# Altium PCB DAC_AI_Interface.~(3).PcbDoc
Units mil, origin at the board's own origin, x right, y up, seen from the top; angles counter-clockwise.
Board outline 2600 x 10000 mil, 4 copper layers (Top Layer, InternalPlane1, InternalPlane2, Bottom Layer); 6 components, 34 nets, 192 pads, 15 vias.
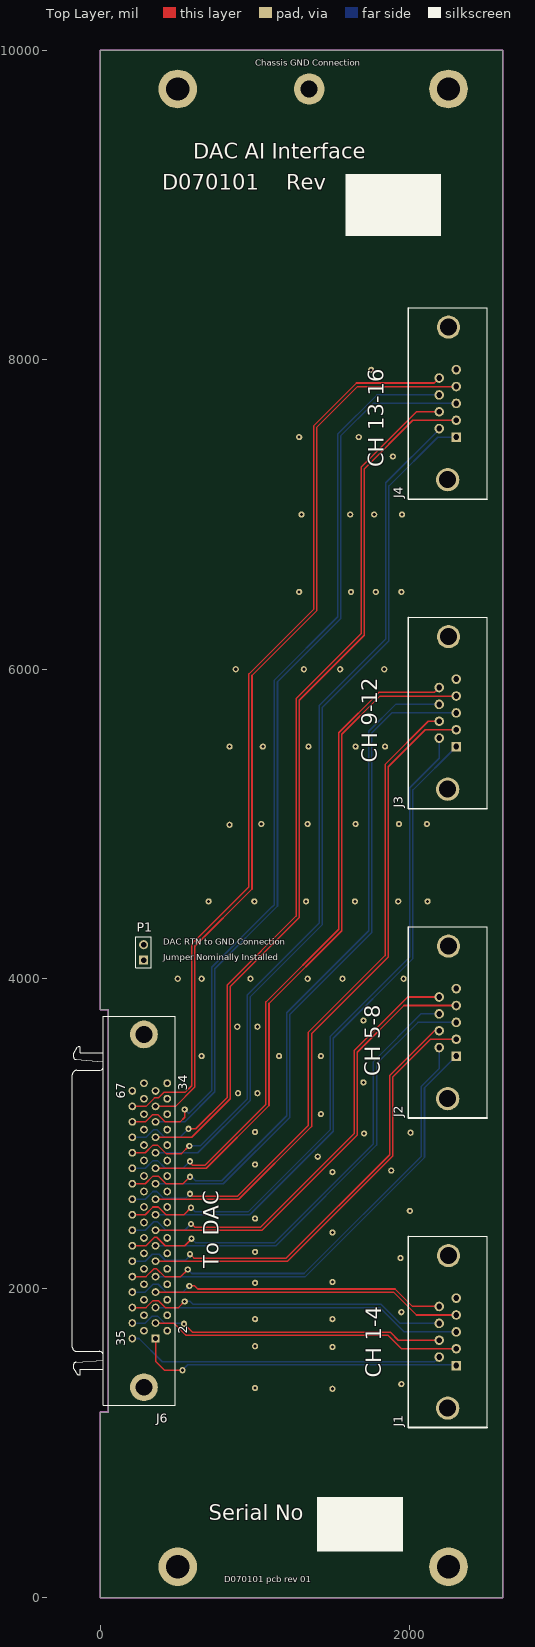
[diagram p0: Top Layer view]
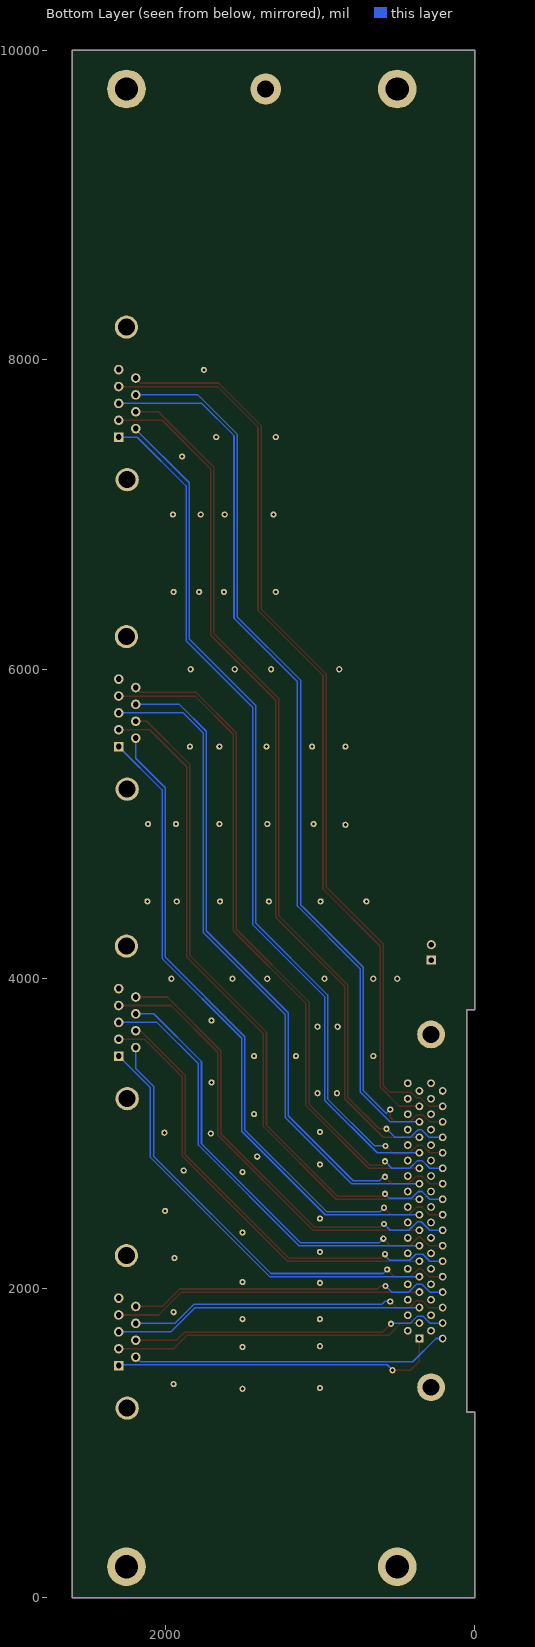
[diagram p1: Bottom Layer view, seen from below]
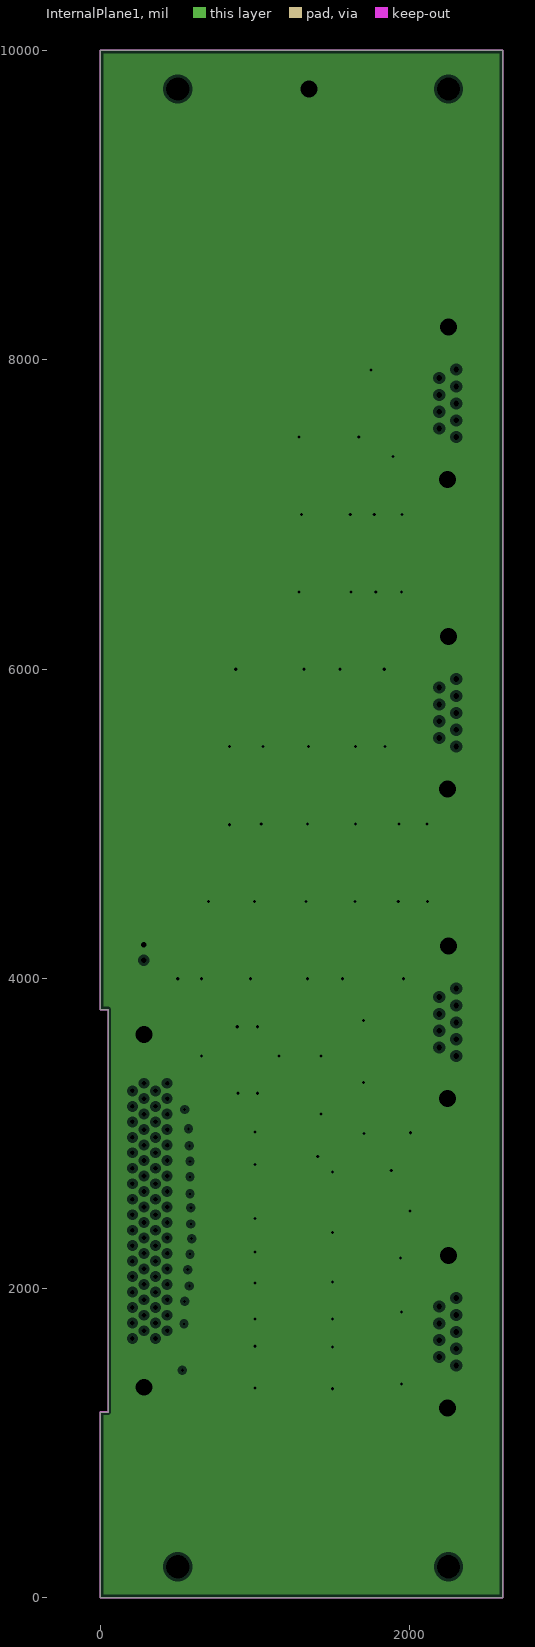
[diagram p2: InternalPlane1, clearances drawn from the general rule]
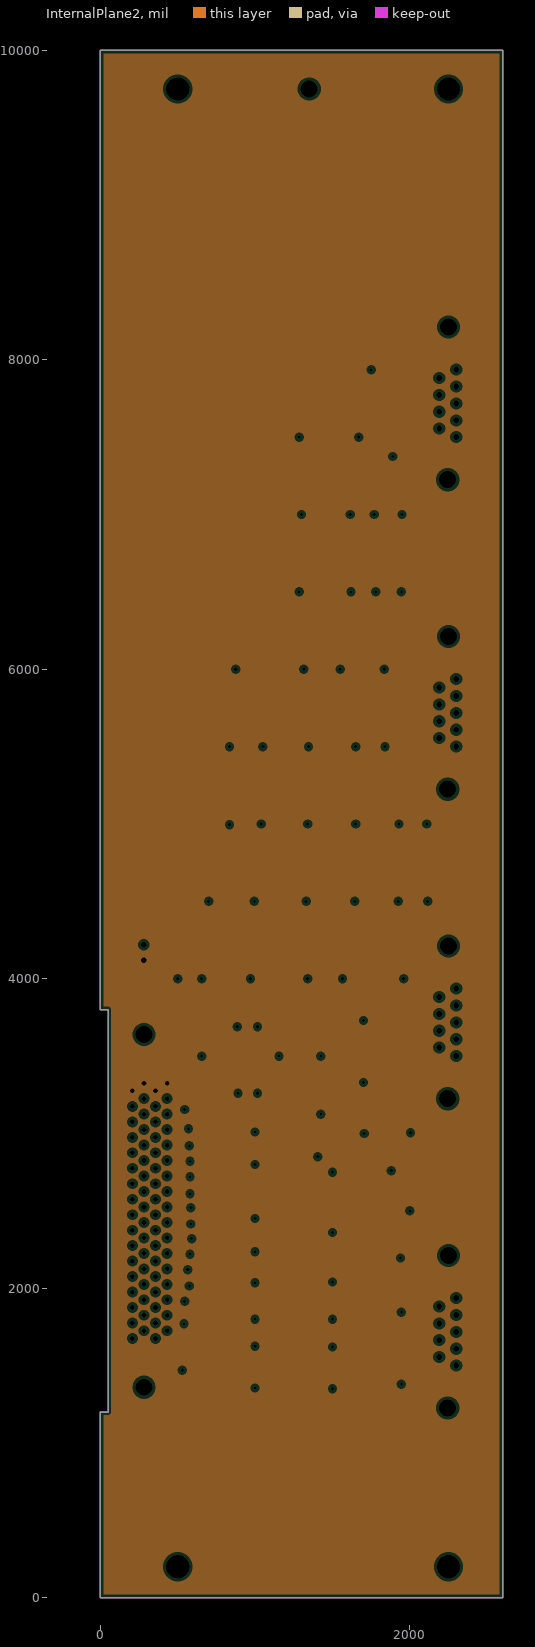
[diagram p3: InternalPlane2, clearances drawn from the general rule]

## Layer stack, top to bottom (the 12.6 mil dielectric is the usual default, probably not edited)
Top Solder: solder mask 0.4, Solder Resist, Dk 3.5
Top Layer: signal copper 1.4
Dielectric1: core 12.6, FR-4, Dk 4.8
InternalPlane1: plane copper 1.4
Dielectric2: prepreg 12.6, FR-4, Dk 4.8
InternalPlane2: plane copper 1.4
Dielectric3: core 12.6, FR-4, Dk 4.8
Bottom Layer: signal copper 1.4
Bottom Solder: solder mask 0.4, Solder Resist, Dk 3.5

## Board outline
0,0 0,1200 50,1200 50,3800 0,3800 0,10000 2600,10000 2600,0

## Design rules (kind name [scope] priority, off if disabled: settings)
Clearance [All] p1: gap=10 ignorepadtopadclearanceinfootprint=FALSE except(0: Arc-Hole Track-Hole SMDPad-Hole THPad-Hole Via-Hole Fill-Hole Poly-Hole Region-Hole Text-Hole)
FabricationTestPointUsage TestPointUsage [All] p1: valid=0 allowmultiple=FALSE
FabricationTestpoint Testpoint [All] p1: side=3 testpointundercomponent=TRUE minsize=40 maxsize=100 preferedsize=60 minholesize=0 maxholesize=40 preferedholesize=32 testpointgrid=1 allowsidetop=TRUE allowsidebottom=TRUE usegrid=TRUE gridtolerance=0.01
HoleSize [All] p1: absolutevalues=TRUE maxlimit=200 minlimit=1 maxpercent=80.000 minpercent=20.000
PlaneClearance [All] p1: clearance=20
PlaneConnect [All] p1: planeconnectstyle=Relief reliefexpansion=20 reliefentries=4 reliefconductorwidth=10 reliefairgap=10
PolygonConnect [All] p1: connectstyle=Relief reliefconductorwidth=10 reliefentries=4 polygonreliefangle="90 Angle" airgapwidth=10
RoutingVias [All] p1: holewidth=20 width=40 viastyle="Through Hole" minholewidth=20 minwidth=40 maxholewidth=28 maxwidth=50
SolderMaskExpansion [All] p1: expansion=4
Width [All] p1: maxlimit=100 minlimit=10 preferedwidth=10
25 further rules are at their usual default settings.

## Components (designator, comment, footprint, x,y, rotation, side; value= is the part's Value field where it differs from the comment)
J1 "5747089-2" DB9/F 2300,1500 r90 top
J2 "5747089-2" DB9/F 2300,3500 r90 top
J3 "5747089-2" DB9/F 2300,5500 r90 top
J4 "5747089-2" DB9/F 2300,7500 r90 top
J6 "787082-7" 787082-7 20,2500 r90 top
P1 "Header 2" HDR1X2 280,4120 r90 top

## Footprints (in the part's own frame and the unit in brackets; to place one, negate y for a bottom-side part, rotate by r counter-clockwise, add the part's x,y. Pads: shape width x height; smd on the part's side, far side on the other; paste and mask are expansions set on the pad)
787082-7 [mm] "Connector; D Subminiature 050 Series; 68 Position; Right Angle"
  rect 1.27x1.27 hole 0.762: 1(-20.955,-8.555)
  round 1.27 hole 0.762: 2(-19.685,-10.46) 3(-18.415,-8.555) 4(-17.145,-10.46) 5(-15.875,-8.555) 6(-14.605,-10.46) 7(-13.335,-8.555) 8(-12.065,-10.46) 9(-10.795,-8.555) 10(-9.525,-10.46) 11(-8.255,-8.555) 12(-6.985,-10.46) 13(-5.715,-8.555) 14(-4.445,-10.46) 15(-3.175,-8.555) 16(-1.905,-10.46) 17(-0.635,-8.555) 18(0.635,-10.46) 19(1.905,-8.555) 20(3.175,-10.46) 21(4.445,-8.555) 22(5.715,-10.46) 23(6.985,-8.555) 24(8.255,-10.46) 25(9.525,-8.555) 26(10.795,-10.46) 27(12.065,-8.555) 28(13.335,-10.46) 29(14.605,-8.555) 30(15.875,-10.46) 31(17.145,-8.555) 32(18.415,-10.46) 33(19.685,-8.555) 34(20.955,-10.46) 35(-20.955,-4.745) 36(-19.685,-6.65) 37(-18.415,-4.745) 38(-17.145,-6.65) 39(-15.875,-4.745) 40(-14.605,-6.65) 41(-13.335,-4.745) 42(-12.065,-6.65) 43(-10.795,-4.745) 44(-9.525,-6.65) 45(-8.255,-4.745) 46(-6.985,-6.65) 47(-5.715,-4.745) 48(-4.445,-6.65) 49(-3.175,-4.745) 50(-1.905,-6.65) 51(-0.635,-4.745) 52(0.635,-6.65) 53(1.905,-4.745) 54(3.175,-6.65) 55(4.445,-4.745) 56(5.715,-6.65) 57(6.985,-4.745) 58(8.255,-6.65) 59(9.525,-4.745) 60(10.795,-6.65) 61(12.065,-4.745) 62(13.335,-6.65) 63(14.605,-4.745) 64(15.875,-6.65) 65(17.145,-4.745) 66(18.415,-6.65) 67(19.685,-4.745) 68(20.955,-6.65)
  round 4.55 hole 2.77: 69(-28.955,-6.65) 70(28.955,-6.65)
  silkscreen extent -31.95,-11.76 31.95,5.11
DB9/F [mil]
  rect 62x62 hole 38: 1(0,0)
  round 62 hole 38: 2(109,0) 3(218,0) 4(327,0) 5(436,0) 6(55,110) 7(164,110) 8(273,110) 9(382,110)
  round 150 hole 110: ""(-275,55) ""(711,50)
  silkscreen extent -400,-200 836,310
HDR1X2 [mm] "Connector; Header; 2 Position"
  rect 1.5x1.5 hole 0.9: 1(0,0)
  round 1.5 hole 0.9: 2(2.54,0)
  silkscreen extent -1.27,-1.27 3.81,1.27

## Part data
J6: "Receptacle Assembly, Shielded, Right Angle, AMPLIMITE"
P1: "Header, 2-Pin"

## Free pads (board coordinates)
  round 200 hole 110: 0(1350,9750)
  round 250 hole 150: 0(2250,200) 1(2250,9750) 2(500,9750) 3(500,200)
  round 40 hole 20: 5(1000,1355) 6(1500,1350) 7(1500,1620) 8(1500,1800) 9(1000,1800) 10(1000,2035) 11(1500,2040) 12(1500,2360) 13(1000,2235) 14(1000,2450) 15(1500,2750) 16(1880,2760) 17(2005,3005) 18(1705,3000) 19(1000,2800) 20(1000,3010) 21(1015,3260) 22(1015,3690) 23(885,3690) 24(890,3260) 25(655,3500) 26(655,4000) 27(970,4000) 28(1340,4000) 29(1565,4000) 30(1960,4000) 31(1700,3330) 32(1405,2850) 33(1425,3125) 34(1425,3500) 35(1700,3730) 36(1155,3500) 37(995,4500) 38(1330,4500) 39(1645,4500) 40(1925,4500) 41(1930,5000) 42(1650,5000) 43(1340,5000) 44(1040,5000) 45(835,4995) 46(700,4500) 47(500,4000) 48(835,5500) 49(1050,5500) 50(1345,5500) 51(1650,5500) 52(1840,5500) 53(1835,6000) 54(1550,6000) 55(1315,6000) 56(875,6000) 57(1620,6500) 58(1780,6500) 59(1945,6500) 60(1285,6500) 61(1300,7000) 62(1615,7000) 63(1770,7000) 64(1950,7000) 65(1890,7375) 66(1670,7500) 67(1285,7500) 68(1750,7935) 69(2115,4500) 70(2110,5000) 71(2000,2500) 72(1945,1845) 73(1945,1380) 74(1940,2195) 75(1000,1625)

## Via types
v1: diameter 40, hole 20, Top Layer to Bottom Layer, 15 vias

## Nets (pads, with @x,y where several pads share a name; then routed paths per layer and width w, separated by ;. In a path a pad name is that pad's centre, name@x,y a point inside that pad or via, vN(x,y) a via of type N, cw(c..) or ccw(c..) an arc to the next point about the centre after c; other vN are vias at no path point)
GND: J1. J2. J3. J4. J6.69 J6.70 P1.2 pad.0@1350,9750 pad.5 pad.6 pad.7 pad.8 pad.9 pad.10 pad.11 pad.12 pad.13 pad.14 pad.15 pad.16 pad.17 pad.18 pad.19 pad.20 pad.21 pad.22 pad.23 pad.24 pad.25 pad.26 pad.27 pad.28 pad.29 pad.30 pad.31 pad.32 pad.33 pad.34 pad.35 pad.36 pad.37 pad.38 pad.39 pad.40 pad.41 pad.42 pad.43 pad.44 pad.45 pad.46 pad.47 pad.48 pad.49 pad.50 pad.51 pad.52 pad.53 pad.54 pad.55 pad.56 pad.57 pad.58 pad.59 pad.60 pad.61 pad.62 pad.63 pad.64 pad.65 pad.66 pad.67 pad.68 pad.69 pad.70 pad.71 pad.72 pad.73 pad.74 pad.75
INPUTN1: J1.6 J6.35 | length 2082.7
  Top Layer w10: J1.6@2165,1555 J1.6
  Bottom Layer w10: J6.35 250,1675 400,1525 2160,1525 J1.6
INPUTN2: J1.7 J6.37 | length 2066.4
  Top Layer w10: v1(540,1770) 595,1715 1875,1715 1926,1664 J1.7
  Bottom Layer w10: J6.37 290,1775 335,1820 370,1820 415,1775 535,1775 v1(540,1770)
INPUTN3: J1.8 J6.39 | length 2095.9
  Top Layer w10: J6.39 295,1875 340,1920 375,1920 420,1875 505,1875 v1(545,1915)
  Bottom Layer w10: v1(545,1915) 580,1915 600,1895 1815,1895 1937,1773 J1.8
INPUTN4: J1.9 J6.41 | length 2096.3
  Top Layer w10: v1(575,2015) 610,2015 630,1995 1905,1995 2018,1882 J1.9
  Bottom Layer w10: J6.41 290,1975 340,2025 375,2025 425,1975 535,1975 v1(575,2015)
INPUTN5: J2.6 J6.43 | length 3002
  Top Layer w10: J6.43 295,2075 345,2125 365,2125 415,2075 520,2075 v1(565,2120)
  Bottom Layer w10: v1(565,2120) 590,2095 1316.72,2095 2075,2853.28 2075,3305 2190,3420 J2.6
INPUTN6: J2.7 J6.45 | length 2959.4
  Top Layer w10: v1(580,2220) 605,2195 1201.72,2195 1870,2863.28 1870,3375 2159,3664 J2.7
  Bottom Layer w10: J6.45 290,2175 335,2220 380,2220 420,2180 550,2180 580,2210 v1(580,2220)
INPUTN7: J2.8 J6.47 | length 2981.4
  Top Layer w10: J6.47 295,2275 350,2330 365,2330 420,2275 545,2275 v1(590,2320)
  Bottom Layer w10: v1(590,2320) 615,2295 1126.72,2295 1765,2933.28 1765,3465 2073,3773 J2.8
INPUTN8: J2.9 J6.49 | length 2983.9
  Top Layer w10: v1(585,2415) 590,2415 610,2395 1036.72,2395 1640,2998.28 1640,3535 1987,3882 J2.9
  Bottom Layer w10: J6.49 290,2375 345,2430 370,2430 425,2375 545,2375 v1(585,2415)
INPUTN9: J3.6 J6.51 | length 4391.2
  Top Layer w10: J6.51 290,2475 340,2525 375,2525 425,2475 540,2475 v1(585,2520)
  Bottom Layer w10: v1(585,2520) 610,2495 956.72,2495 1485,3023.28 1485,3625 2000,4140 2000,5235 2190,5425 J3.6
INPUTN10: J3.7 J6.53 | length 4388.3
  Top Layer w10: v1(580,2610) 595,2595 886.72,2595 1345,3053.28 1345,3655 1840,4150 1840,5385 2119,5664 J3.7
  Bottom Layer w10: J6.53 290,2575 340,2625 365,2625 410,2580 550,2580 v1(580,2610)
INPUTN11: J3.8 J6.55 | length 4473.8
  Top Layer w10: J6.55 290,2675 340,2725 375,2725 425,2675 535,2675 v1(580,2720)
  Bottom Layer w10: v1(580,2720) 590,2720 615,2695 785,2695 1205,3115 1205,3780 1735,4310 1735,5600 1908,5773 J3.8
INPUTN12: J3.9 J6.57 | length 4469.7
  Top Layer w10: v1(580,2820) 580,2810 595,2795 676.72,2795 1070,3188.28 1070,3850 1540,4320 1540,5590 1800,5850 2158,5850 J3.9
  Bottom Layer w10: J6.57 290,2775 340,2825 370,2825 420,2775 535,2775 v1(580,2820)
INPUTN13: J4.6 J6.59 | length 5778.4
  Top Layer w10: J6.59 290,2875 340,2925 370,2925 425,2870 525,2870 v1(575,2920)
  Bottom Layer w10: v1(575,2920) 646.72,2920 950,3223.28 950,3895 1415,4360 1415,5765 1845,6195 1845,7205 2190,7550 J4.6
INPUTN14: J4.7 J6.61 | length 5845.3
  Top Layer w10: v1(570,3030) 616.72,3030 820,3233.28 820,3960 1265,4405 1265,5810 1685,6230 1685,7305 2044,7664 J4.7
  Bottom Layer w10: J6.61 295,2975 345,3025 365,3025 415,2975 515,2975 v1(570,3030)
INPUTN15: J4.8 J6.63 | length 6025.5
  Top Layer w10: J6.63 290,3075 335,3120 375,3120 420,3075 515,3075 545,3105 v1(545,3155)
  Bottom Layer w10: v1(545,3155) 570.86,3129.14 720,3278.28 720,4075 1110,4465 1111.72,4465 1125,4478.28 1125,5930 1535,6340 1535,7520 1788,7773 J4.8
INPUTN16: J4.9 J6.65 | length 5969.5
  Top Layer w10: J6.65 295,3175 350,3230 375,3230 410,3265 546.72,3265 590,3308.28 590,4225 960,4595 960,5970 1380,6390 1380,7575 1655,7850 2158,7850 J4.9
INPUTP1: J1.1 J6.1 | length 2130.7
  Top Layer w10: J6.1 356.81,1528.19 415,1470 v1(530,1470)
  Bottom Layer w10: v1(530,1470) 565,1505 2295,1505 J1.1
INPUTP2: J1.2 J6.3 | length 2011.9
  Top Layer w10: J6.3 475,1775 555,1695 1860,1695 1946,1609 J1.2
INPUTP3: J1.3 J6.5 | length 2008.2
  Bottom Layer w10: J6.5 1805,1875 1962,1718 J1.3
INPUTP4: J1.4 J6.7 | length 2004.5
  Top Layer w10: J6.7 1895,1975 2043,1827 J1.4
INPUTP5: J2.1 J6.9 | length 2797
  Bottom Layer w10: J6.9 1325,2075 2095,2845 2095,3295 J2.1
INPUTP6: J2.2 J6.11 | length 2835.9
  Top Layer w10: J6.11 1210,2175 1890,2855 1890,3365 2134,3609 J2.2
INPUTP7: J2.3 J6.13 | length 2848.4
  Bottom Layer w10: J6.13 1135,2275 1785,2925 1785,3450 2053,3718 J2.3
INPUTP8: J2.4 J6.15 | length 2858
  Top Layer w10: J6.15 1045,2375 1660,2990 1660,3525 1962,3827 J2.4
INPUTP9: J3.1 J6.17 | length 4186.2
  Bottom Layer w10: J6.17 965,2475 1505,3015 1505,3615 2020,4130 2020,5220 J3.1
INPUTP10: J3.2 J6.19 | length 4271.9
  Top Layer w10: J6.19 895,2575 1365,3045 1365,3645 1860,4140 1860,5370 2099,5609 J3.2
INPUTP11: J3.3 J6.21 | length 4348.9
  Bottom Layer w10: J6.21 795,2675 1225,3105 1225,3770 1755,4300 1755,5590 1883,5718 J3.3
INPUTP12: J3.4 J6.23 | length 4337.9
  Top Layer w10: J6.23 685,2775 1090,3180 1090,3840 1560,4310 1560,5580 1807,5827 J3.4
INPUTP13: J4.1 J6.25 | length 5660.2
  Bottom Layer w10: J6.25 630,2875 970,3215 970,3885 1435,4350 1435,5755 1865,6185 1865,7185 2180,7500 J4.1
INPUTP14: J4.2 J6.27 | length 5740.1
  Top Layer w10: J6.27 590,2975 840,3225 840,3950 1285,4395 1285,5800 1705,6220 1705,7295 2019,7609 J4.2
INPUTP15: J4.3 J6.29 | length 5872.7
  Bottom Layer w10: J6.29 545,3075 740,3270 740,4065 1145,4470 1145,5920 1555,6330 1555,7510 1763,7718 J4.3
INPUTP16: J4.4 J6.31 | length 5905.7
  Top Layer w10: J6.31 485,3175 610,3300 610,4210 980,4580 980,5960 1400,6380 1400,7565 1662,7827 J4.4
INPUTRTN: J6.33 J6.34 J6.67 J6.68 P1.1
pads on no net: J1.5 J2.5 J3.5 J4.5 J6.2 J6.4 J6.6 J6.8 J6.10 J6.12 J6.14 J6.16 J6.18 J6.20 J6.22 J6.24 J6.26 J6.28 J6.30 J6.32 J6.36 J6.38 J6.40 J6.42 J6.44 J6.46 J6.48 J6.50 J6.52 J6.54 J6.56 J6.58 J6.60 J6.62 J6.64 J6.66

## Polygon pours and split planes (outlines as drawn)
GND on InternalPlane1 (split plane): 2579.9,20.1 20.1,20.1 20.1,1179.9 50,1179.9 53.92,1180.29 57.69,1181.43 61.17,1183.29 64.21,1185.79 66.71,1188.83 68.57,1192.31 69.71,1196.08 70.1,1200 70.1,3800 69.71,3803.92 68.57,3807.69 66.71,3811.17 64.21,3814.21 61.17,3816.71 57.69,3818.57 53.92,3819.71 50,3820.1 20.1,3820.1 20.1,9979.9 2579.9,9979.9
INPUTRTN on InternalPlane2 (split plane): 2579.9,20.1 20.1,20.1 20.1,1179.9 50,1179.9 53.92,1180.29 57.69,1181.43 61.17,1183.29 64.21,1185.79 66.71,1188.83 68.57,1192.31 69.71,1196.08 70.1,1200 70.1,3800 69.71,3803.92 68.57,3807.69 66.71,3811.17 64.21,3814.21 61.17,3816.71 57.69,3818.57 53.92,3819.71 50,3820.1 20.1,3820.1 20.1,9979.9 2579.9,9979.9

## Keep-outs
Keep-Out Layer:
  the board outline again, w10

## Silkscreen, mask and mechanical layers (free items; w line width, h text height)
Top Overlay:
  rectangle: 1585,8800 2200,9200
  rectangle: 1400,300 1955,650
  text "Chassis GND Connection" at 1000,9900 h40
  text "DAC AI Interface" at 600,9300 h100
  text "D070101" at 400,9100 h100
  text "Rev" at 1200,9100 h100
  text "CH 13-16" at 1830,7305 h100 r90
  text "CH 9-12" at 1790,5395 h100 r90
  text "DAC RTN to GND Connection" at 405,4220 h40
  text "Jumper Nominally Installed" at 405,4120 h40
  text "CH 5-8" at 1810,3370 h100 r90
  text "To DAC" at 765,2130 h100 r90
  text "CH 1-4" at 1815,1420 h100 r90
  text "Serial No" at 700,500 h100
  text "D070101 pcb rev 01" at 800,100 h40
Mechanical 1:
  lines w10: 0,0 2600,0 2600,10000 0,10000 0,3800 50,3800 50,2500 50,1200 0,1200 0,0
